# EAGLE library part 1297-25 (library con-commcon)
.800" BOARD SPACE 2mm CONNECTORS - HI TEMP TWO ROW 2mm - NON-STACKTHROUGH
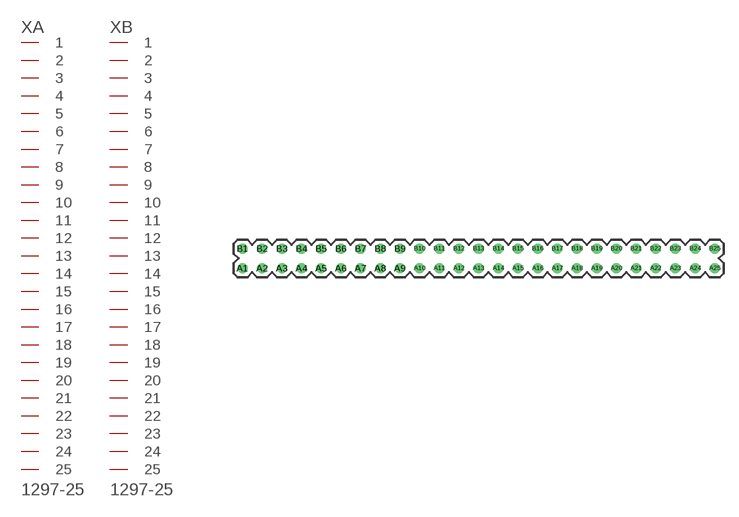
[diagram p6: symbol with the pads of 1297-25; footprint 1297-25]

Designator prefix X; gates A=PIN25 B=PIN25

## 1297-25 (OC_FARNELL: unknown; OC_NEWARK: unknown)  [1297-25]
A1  A:1  pas
A2  A:2  pas
A3  A:3  pas
A4  A:4  pas
A5  A:5  pas
A6  A:6  pas
A7  A:7  pas
A8  A:8  pas
A9  A:9  pas
A10  A:10  pas
A11  A:11  pas
A12  A:12  pas
A13  A:13  pas
A14  A:14  pas
A15  A:15  pas
A16  A:16  pas
A17  A:17  pas
A18  A:18  pas
A19  A:19  pas
A20  A:20  pas
A21  A:21  pas
A22  A:22  pas
A23  A:23  pas
A24  A:24  pas
A25  A:25  pas
B1  B:1  pas
B2  B:2  pas
B3  B:3  pas
B4  B:4  pas
B5  B:5  pas
B6  B:6  pas
B7  B:7  pas
B8  B:8  pas
B9  B:9  pas
B10  B:10  pas
B11  B:11  pas
B12  B:12  pas
B13  B:13  pas
B14  B:14  pas
B15  B:15  pas
B16  B:16  pas
B17  B:17  pas
B18  B:18  pas
B19  B:19  pas
B20  B:20  pas
B21  B:21  pas
B22  B:22  pas
B23  B:23  pas
B24  B:24  pas
B25  B:25  pas

## Footprint 1297-25 (pad centres in mm)
.800" BOARD SPACE 2mm CONNECTORS - HI TEMP TWO ROW 2mm - NON-STACKTHROUGH
drill 0.508 round: A1 -24,-1; A2 -22,-1; A3 -20,-1; A4 -18,-1; A5 -16,-1; A6 -14,-1; A7 -12,-1; A8 -10,-1; A9 -8,-1; A10 -6,-1; A11 -4,-1; A12 -2,-1; A13 0,-1; A14 2,-1; A15 4,-1; A16 6,-1; A17 8,-1; A18 10,-1; A19 12,-1; A20 14,-1; A21 16,-1; A22 18,-1; A23 20,-1; A24 22,-1; A25 24,-1; B1 -24,1; B2 -22,1; B3 -20,1; B4 -18,1; B5 -16,1; B6 -14,1; B7 -12,1; B8 -10,1; B9 -8,1; B10 -6,1; B11 -4,1; B12 -2,1; B13 0,1; B14 2,1; B15 4,1; B16 6,1; B17 8,1; B18 10,1; B19 12,1; B20 14,1; B21 16,1; B22 18,1; B23 20,1; B24 22,1; B25 24,1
